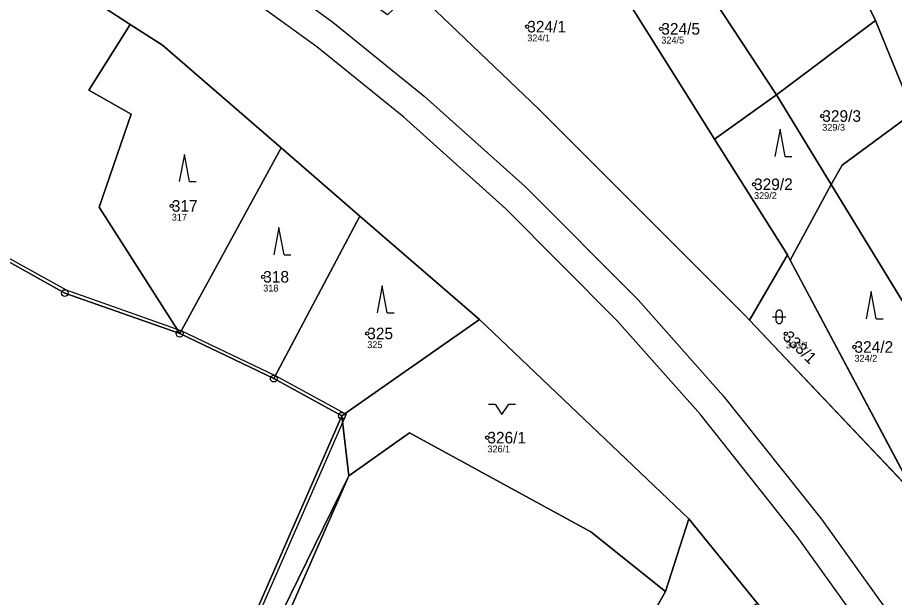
# Model space of a CAD drawing. Extents: x -770088 to -765625, y -1057899 to -1053934.
# Drawn here: x -766391.1 to -766262.3, y -1055089.8 to -1055004.6 of the extents above; entities that cross this region are included whole.
import ezdxf

# ---------------------------------------------------------------- set-up
doc = ezdxf.new("R2010")
doc.units = 0
for name, color, linetype in [('Definiční body', 7, 'Continuous'), ('Hranice parcel', 7, 'Continuous'), ('Parcelní čísla', 7, 'Continuous'), ('Polygon parcely', 7, 'Continuous'), ('Poz předměty', 7, 'Continuous'), ('Vnitřní kresba', 7, 'Continuous'), ('Značky bodu BP', 7, 'Continuous'), ('Značky kultur', 7, 'Continuous')]:
    doc.layers.add(name, color=color, linetype=linetype)

msp = doc.modelspace()

# ---------------------------------------------------------------- linework, layer by layer
at = {"layer": 'Definiční body'}
for centre in [(-766316.28, -1055005.94), (-766296.59, -1055006.26), (-766272.95, -1055019.07), (-766282.97, -1055029.1), (-766368.49, -1055032.28), (-766355.06, -1055042.69), (-766339.78, -1055051.01), (-766278.29, -1055051.05), (-766268.22, -1055053), (-766322.14, -1055066.32)]:
    msp.add_circle(centre, 0.25, dxfattribs=at)
at = {"layer": 'Hranice parcel'}
for p, q in [((-766369.87, -1055008.68), (-766374.59, -1055005.6)), ((-766279.68, -1055015.95), (-766265.13, -1055005.05)), ((-766265.13, -1055005.05), (-766259.61, -1055018.61)), ((-766352.44, -1055023.76), (-766369.87, -1055008.68)), ((-766288.76, -1055022.46), (-766279.68, -1055015.95)), ((-766271.63, -1055029.13), (-766279.68, -1055015.95)), ((-766288.76, -1055022.46), (-766292.21, -1055016.97)), ((-766278.07, -1055039.44), (-766288.76, -1055022.46)), ((-766367.33, -1055051.04), (-766352.44, -1055023.76)), ((-766340.86, -1055033.78), (-766352.44, -1055023.76)), ((-766271.63, -1055029.13), (-766277.64, -1055040.25)), ((-766256.48, -1055053.98), (-766271.63, -1055029.13)), ((-766353.51, -1055057.64), (-766340.86, -1055033.78)), ((-766323.3, -1055048.97), (-766340.86, -1055033.78)), ((-766283.66, -1055049.06), (-766278.07, -1055039.44)), ((-766277.64, -1055040.25), (-766278.07, -1055039.44)), ((-766277.64, -1055040.25), (-766259.31, -1055074.75)), ((-766343.5, -1055063.11), (-766323.3, -1055048.97)), ((-766323.3, -1055048.97), (-766292.55, -1055078.27)), ((-766284.39, -1055048.29), (-766283.66, -1055049.06)), ((-766283.66, -1055049.06), (-766259.31, -1055074.75)), ((-766353.51, -1055057.64), (-766367.33, -1055051.04)), ((-766343.5, -1055063.11), (-766353.51, -1055057.64)), ((-766342.46, -1055071.93), (-766343.5, -1055063.11)), ((-766351.2, -1055091.79), (-766342.46, -1055071.93)), ((-766295.99, -1055088.92), (-766292.55, -1055078.27)), ((-766292.55, -1055078.27), (-766282.47, -1055090.68)), ((-766305.69, -1055106.15), (-766295.99, -1055088.92))]:
    msp.add_line(p, q, dxfattribs=at)
for points in [[(-766265.13, -1055005.05), (-766275.94, -1054982.78), (-766288.47, -1054963.18)], [(-766303.86, -1054980.9), (-766290.05, -1055000.12), (-766279.68, -1055015.95)], [(-766374.59, -1055005.6), (-766391.17, -1054994.8), (-766410.72, -1054984.88)], [(-766292.21, -1055016.97), (-766305.46, -1054995.85), (-766309.99, -1054988.4)], [(-766332.95, -1055000.5), (-766314.61, -1055018.03), (-766284.39, -1055048.29)], [(-766367.33, -1055051.04), (-766379.13, -1055032.45), (-766374.44, -1055018.81), (-766380.66, -1055015.27), (-766374.59, -1055005.6)], [(-766367.33, -1055051.04), (-766384.2, -1055045.08), (-766396.48, -1055038.26), (-766400.19, -1055034.96), (-766405.66, -1055025.57), (-766403.91, -1055016.18)], [(-766259.61, -1055018.61), (-766270.01, -1055026.29), (-766271.63, -1055029.13)], [(-766374.22, -1055155.77), (-766365.35, -1055118.73), (-766363.61, -1055109.08), (-766343.5, -1055063.11)], [(-766342.46, -1055071.93), (-766333.55, -1055065.59), (-766306.93, -1055080.18), (-766295.99, -1055088.92)], [(-766342.46, -1055071.93), (-766359.77, -1055107.18), (-766365.55, -1055134.66), (-766371.79, -1055156.12), (-766389.45, -1055195.81)]]:
    msp.add_lwpolyline(points, dxfattribs=at)
at = {"layer": 'Polygon parcely'}
for points in [[(-766744.81, -1054852.9), (-766703.76, -1054844.77), (-766655.14, -1054838.66), (-766521.36, -1054825.96), (-766503.44, -1054826.8), (-766486.19, -1054829.35), (-766469.46, -1054833.29), (-766422.64, -1054849.83), (-766390.58, -1054867.14), (-766367, -1054883.93), (-766343.3, -1054902.14), (-766327.48, -1054917.77), (-766312.88, -1054933.4), (-766310.69, -1054935.75), (-766309.32, -1054937.22), (-766303.69, -1054943.24), (-766299.33, -1054948.96), (-766297.55, -1054951.29), (-766288.47, -1054963.18), (-766275.94, -1054982.78), (-766265.13, -1055005.05), (-766259.61, -1055018.61)], [(-766259.31, -1055074.75), (-766283.66, -1055049.06), (-766284.39, -1055048.29), (-766314.61, -1055018.03), (-766332.95, -1055000.5), (-766336.8, -1055004.2), (-766377.76, -1054974.79), (-766375.64, -1054970.45), (-766375.06, -1054966.02), (-766357.78, -1054973.56), (-766342.5, -1054978.1), (-766340.25, -1054978.68), (-766337.29, -1054979.45), (-766331.99, -1054977.53), (-766326.97, -1054980.5), (-766319.71, -1054972.41), (-766321.9, -1054969.1), (-766330.38, -1054956.29), (-766344.38, -1054942.1), (-766350.81, -1054944.93), (-766354.58, -1054941.6), (-766355.68, -1054945.89)], [(-766727.95, -1054957.74), (-766584.45, -1054947.2), (-766504.07, -1054949.49), (-766435.23, -1054967.27), (-766416.1, -1054974.32), (-766412.53, -1054978.92), (-766412.18, -1054979.84), (-766411.17, -1054982.44), (-766410.78, -1054983.45), (-766410.72, -1054984.88), (-766391.17, -1054994.8), (-766374.59, -1055005.6), (-766369.87, -1055008.68), (-766352.44, -1055023.76), (-766340.86, -1055033.78), (-766323.3, -1055048.97), (-766292.55, -1055078.27), (-766282.47, -1055090.68), (-766262.46, -1055116.52), (-766228.83, -1055168.55)], [(-766519.51, -1055129.3), (-766483.88, -1055132.2), (-766452.16, -1055132.72), (-766425.08, -1055139.27), (-766395.04, -1055149.22), (-766374.22, -1055155.77), (-766365.35, -1055118.73), (-766363.61, -1055109.08), (-766343.5, -1055063.11), (-766353.51, -1055057.64), (-766367.33, -1055051.04), (-766384.2, -1055045.08), (-766396.48, -1055038.26), (-766400.19, -1055034.96), (-766405.66, -1055025.57), (-766403.91, -1055016.18), (-766419.48, -1055017.32), (-766522.85, -1054989.19)]]:
    msp.add_lwpolyline(points, dxfattribs=at)
for points in [[(-766290.05, -1055000.12), (-766279.68, -1055015.95), (-766265.13, -1055005.05), (-766275.94, -1054982.78), (-766288.47, -1054963.18), (-766303.86, -1054980.9)], [(-766326.97, -1054980.5), (-766326.01, -1054981.63), (-766320.28, -1054988.33), (-766332.95, -1055000.5), (-766314.61, -1055018.03), (-766284.39, -1055048.29), (-766283.66, -1055049.06), (-766278.07, -1055039.44), (-766288.76, -1055022.46), (-766292.21, -1055016.97), (-766305.46, -1054995.85), (-766309.99, -1054988.4), (-766319.71, -1054972.41)], [(-766279.68, -1055015.95), (-766290.05, -1055000.12), (-766303.86, -1054980.9), (-766309.99, -1054988.4), (-766305.46, -1054995.85), (-766292.21, -1055016.97), (-766288.76, -1055022.46)], [(-766391.17, -1054994.8), (-766410.72, -1054984.88), (-766403.91, -1055016.18), (-766405.66, -1055025.57), (-766400.19, -1055034.96), (-766396.48, -1055038.26), (-766384.2, -1055045.08), (-766367.33, -1055051.04), (-766379.13, -1055032.45), (-766374.44, -1055018.81), (-766380.66, -1055015.27), (-766374.59, -1055005.6)], [(-766374.59, -1055005.6), (-766380.66, -1055015.27), (-766374.44, -1055018.81), (-766379.13, -1055032.45), (-766367.33, -1055051.04), (-766352.44, -1055023.76), (-766369.87, -1055008.68)], [(-766265.13, -1055005.05), (-766279.68, -1055015.95), (-766271.63, -1055029.13), (-766270.01, -1055026.29), (-766259.61, -1055018.61)], [(-766271.63, -1055029.13), (-766279.68, -1055015.95), (-766288.76, -1055022.46), (-766278.07, -1055039.44), (-766277.64, -1055040.25)], [(-766270.01, -1055026.29), (-766271.63, -1055029.13), (-766256.48, -1055053.98), (-766252.75, -1055063.17), (-766250.95, -1055066.45), (-766246.22, -1055052.82), (-766259.61, -1055018.61)], [(-766352.44, -1055023.76), (-766367.33, -1055051.04), (-766353.51, -1055057.64), (-766340.86, -1055033.78)], [(-766277.64, -1055040.25), (-766259.31, -1055074.75), (-766255.11, -1055082.14), (-766254.29, -1055083.55), (-766251.21, -1055071.89), (-766250.15, -1055067.9), (-766250.95, -1055066.45), (-766252.75, -1055063.17), (-766256.48, -1055053.98), (-766271.63, -1055029.13)], [(-766340.86, -1055033.78), (-766353.51, -1055057.64), (-766343.5, -1055063.11), (-766323.3, -1055048.97)], [(-766283.66, -1055049.06), (-766259.31, -1055074.75), (-766277.64, -1055040.25), (-766278.07, -1055039.44)], [(-766306.93, -1055080.18), (-766295.99, -1055088.92), (-766292.55, -1055078.27), (-766323.3, -1055048.97), (-766343.5, -1055063.11), (-766342.46, -1055071.93), (-766333.55, -1055065.59)], [(-766342.46, -1055071.93), (-766343.5, -1055063.11), (-766363.61, -1055109.08), (-766365.35, -1055118.73), (-766374.22, -1055155.77), (-766391.12, -1055195.24), (-766389.45, -1055195.81), (-766371.79, -1055156.12), (-766365.55, -1055134.66), (-766359.77, -1055107.18)], [(-766351.2, -1055091.79), (-766325.85, -1055141.98), (-766305.69, -1055106.15), (-766295.99, -1055088.92), (-766306.93, -1055080.18), (-766333.55, -1055065.59), (-766342.46, -1055071.93)], [(-766351.2, -1055091.79), (-766342.46, -1055071.93), (-766359.77, -1055107.18), (-766365.55, -1055134.66), (-766371.79, -1055156.12), (-766389.45, -1055195.81), (-766387.95, -1055196.32), (-766369.7, -1055158.11), (-766363.4, -1055135.63), (-766358.63, -1055109.47)], [(-766282.47, -1055090.68), (-766292.55, -1055078.27), (-766295.99, -1055088.92), (-766305.69, -1055106.15), (-766295.16, -1055115.97), (-766292.59, -1055108.26), (-766284.58, -1055091.77)]]:
    msp.add_lwpolyline(points, close=True, dxfattribs=at)
at = {"layer": 'Poz předměty'}
for p, q in [((-766361.62, -1054993.07), (-766344.81, -1055005.3)), ((-766347.2, -1055008.92), (-766364.15, -1054996.59)), ((-766344.81, -1055005.3), (-766331.41, -1055016.15)), ((-766334.41, -1055019.26), (-766347.2, -1055008.92)), ((-766331.41, -1055016.15), (-766316.54, -1055029.45)), ((-766319.41, -1055032.69), (-766334.41, -1055019.26)), ((-766316.54, -1055029.45), (-766300, -1055046.09)), ((-766303.1, -1055049.09), (-766319.41, -1055032.69)), ((-766300, -1055046.09), (-766287.49, -1055060.17)), ((-766290.83, -1055062.92), (-766303.1, -1055049.09)), ((-766287.49, -1055060.17), (-766273.06, -1055078.29)), ((-766276.63, -1055080.83), (-766290.83, -1055062.92)), ((-766273.06, -1055078.29), (-766258.94, -1055097.95)), ((-766262.86, -1055100), (-766276.63, -1055080.83))]:
    msp.add_line(p, q, dxfattribs=at)
at = {"layer": 'Vnitřní kresba'}
for p, q in [((-766396.19, -1055037.85), (-766383.99, -1055044.62)), ((-766383.99, -1055044.62), (-766367.16, -1055050.57)), ((-766367.16, -1055050.57), (-766353.23, -1055057.22)), ((-766353.23, -1055057.22), (-766342.86, -1055062.89)), ((-766342.86, -1055062.89), (-766363.13, -1055109.23))]:
    msp.add_line(p, q, dxfattribs=at)
at = {"layer": 'Značky bodu BP'}
for centre, radius in [((-766384.2, -1055045.08), 0.5), ((-766384.2, -1055045.08), 0.0303), ((-766367.33, -1055051.04), 0.5), ((-766367.33, -1055051.04), 0.0303), ((-766353.51, -1055057.64), 0.5), ((-766353.51, -1055057.64), 0.0303), ((-766343.5, -1055063.11), 0.5), ((-766343.5, -1055063.11), 0.0303)]:
    msp.add_circle(centre, radius, dxfattribs=at)
at = {"layer": 'Značky kultur'}
for p, q in [((-766279.15, -1055021), (-766279.9, -1055025)), ((-766278.4, -1055025), (-766279.15, -1055021)), ((-766366.64, -1055024.7), (-766367.39, -1055028.7)), ((-766365.89, -1055028.7), (-766366.64, -1055024.7)), ((-766278.4, -1055025), (-766277.4, -1055025)), ((-766365.89, -1055028.7), (-766364.89, -1055028.7)), ((-766352.75, -1055035.45), (-766353.5, -1055039.45)), ((-766352, -1055039.45), (-766352.75, -1055035.45)), ((-766352, -1055039.45), (-766351, -1055039.45)), ((-766337.58, -1055044), (-766338.33, -1055048)), ((-766336.83, -1055048), (-766337.58, -1055044)), ((-766265.76, -1055044.87), (-766266.51, -1055048.87)), ((-766265.01, -1055048.87), (-766265.76, -1055044.87)), ((-766336.83, -1055048), (-766335.83, -1055048)), ((-766279.78, -1055048.07), (-766279.78, -1055049.07)), ((-766278.78, -1055049.07), (-766278.78, -1055048.07)), ((-766280.28, -1055048.57), (-766278.28, -1055048.57)), ((-766265.01, -1055048.87), (-766264.01, -1055048.87)), ((-766321.99, -1055061.41), (-766320.99, -1055061.41)), ((-766320.99, -1055061.41), (-766319.99, -1055062.91)), ((-766319.99, -1055062.91), (-766318.99, -1055061.41)), ((-766318.99, -1055061.41), (-766317.99, -1055061.41))]:
    msp.add_line(p, q, dxfattribs=at)
for centre, start, end in [((-766279.28, -1055048.07), 0, 180), ((-766279.28, -1055049.07), 180, 359.9879)]:
    msp.add_arc(centre, 0.5, start, end, dxfattribs=at)

# ---------------------------------------------------------------- texts
at = {"layer": 'Definiční body'}
for s, p in [('324/1', (-766316.28, -1055008.1)), ('324/5', (-766296.59, -1055008.42)), ('329/3', (-766272.95, -1055021.23)), ('329/2', (-766282.97, -1055031.26)), ('317', (-766368.49, -1055034.44)), ('318', (-766355.06, -1055044.85)), ('325', (-766339.78, -1055053.17)), ('333/1', (-766278.29, -1055053.21)), ('324/2', (-766268.22, -1055055.16)), ('326/1', (-766322.14, -1055068.48))]:
    msp.add_text(s, height=1, dxfattribs=at).set_placement(p)
at = {"layer": 'Parcelní čísla'}
for s, p in [('324/1', (-766316.28, -1055006.79)), ('324/5', (-766296.59, -1055007.11)), ('329/3', (-766272.95, -1055019.92)), ('329/2', (-766282.97, -1055029.95)), ('317', (-766368.49, -1055033.13)), ('318', (-766355.06, -1055043.54)), ('325', (-766339.78, -1055051.86)), ('324/2', (-766268.22, -1055053.85)), ('326/1', (-766322.14, -1055067.17))]:
    msp.add_text(s, height=1.7, dxfattribs=at).set_placement(p)
msp.add_text('333/1', height=1.7, rotation=316, dxfattribs=at).set_placement((-766278.88, -1055051.66))

doc.saveas('drawing.dxf')
